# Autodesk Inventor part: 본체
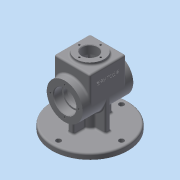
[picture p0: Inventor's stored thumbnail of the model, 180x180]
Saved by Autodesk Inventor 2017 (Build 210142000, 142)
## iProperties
Created: 2020-07
Part Number: 본체
Material: 알루미늄 6061
Document SubType Name: Modeling
Designer: mduedu
Density: 2.71 g/cm^3
Appearance: 기본값
Mass: 1025.32 g
Surface Area: 854.574 cm^2
Volume: 378.346 cm^3
Author: mduedu
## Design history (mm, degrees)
sketch "스케치1"
  geometry: C1 r 32 at (0, 0); 1 further point
  constraints: 1 centre point, 1 coincident
  dimensions: "d0" = 64 diameter of C1
extrude "돌출1" new body sketch "스케치1" stored distance "d1" = 90; taper "d2" = 0 deg
sketch "스케치3"
  geometry: L1 (0, -32)-(50, -32); L2 (50, -32)-(50, 32); L3 (50, 32)-(0, 32); L4 (0, 32)-(0, -32); C1 r 32 at (0, 0) reference; 2 further points
  constraints: 8 end point, 2 parallel, 1 coincident, 1 horizontal, 1 midpoint, 1 perpendicular, 1 tangent
  dimensions: "d5" = 50 distance of L2.end L3.end
extrude "돌출2" join sketch "스케치3" stored distance "d7" = 64; taper "d8" = 0 deg
sketch "스케치4"
  geometry: C1 r 25 at (32, 32); 1 further point
  constraints: 1 centre point, 1 coincident
  dimensions: "d9" = 50 diameter of C1
extrude "돌출3" join sketch "스케치4" distance "d10" = 5; taper "d11" = 0 deg
sketch "스케치5"
  geometry: L1 (0, -25)-(40, -25); L2 (40, -25)-(40, 25); L3 (40, 25)-(0, 25); L4 (0, 25)-(0, -25); L5 (55, -25)-(55, 25) reference; A1 r 25 centre (0, 0) between (0, 25) and (0, -25); A2 r 25 centre (0, 0) between (0, -25) and (0, 25); 2 further points
  constraints: 8 end point, 4 point on circle, 2 centre point, 2 coincident, 2 parallel, 1 horizontal, 1 midpoint, 1 perpendicular, 1 tangent
  dimensions: "d12" = 50 diameter of A1; "d13" = 15 distance between parallel lines of L2 L5
extrude "돌출4" cut sketch "스케치5" stored distance "d14" = 48; taper "d15" = 0 deg
sketch "스케치6"
  geometry: C1 r 20 at (0, 0); 1 further point
  constraints: 1 centre point, 1 coincident
  dimensions: "d16" = 40 diameter of C1
extrude "돌출5" cut sketch "스케치6" distance "d17" = 15; taper "d18" = 0 deg
sketch "스케치7"
  geometry: C1 r 17 at (0, 0); 1 further point
  constraints: 1 centre point, 1 coincident
  dimensions: "d19" = 34 diameter of C1
extrude "돌출6" cut sketch "스케치7" stored distance "d20" = 15; taper "d21" = 0 deg
fillet "모깎기1" dims "d22" = 3
fillet "모깎기2" dims "d23" = 3
fillet "모깎기3" dims "d24" = 3
fillet "모깎기4" dims "d25" = 3
fillet "모깎기5" dims "d26" = 3
sketch "스케치8"
  geometry: C1 r 14 at (0, 0); 1 further point
  constraints: 1 centre point, 1 coincident
  dimensions: "d27" = 28 diameter of C1
extrude "돌출7" cut sketch "스케치8" stored distance "d28" = 15; taper "d29" = 0 deg
node "작업 평면1"
sketch "스케치9"
  geometry: C1 r 67.5 at (0, 0); 1 further point
  constraints: 1 centre point, 1 coincident
  dimensions: "d31" = 135 diameter of C1
extrude "돌출8" join sketch "스케치9" distance "d33" = 10; taper "d34" = 0 deg
sketch "스케치10"
  geometry: C1 r 15 at (0, 0); 1 further point
  constraints: 1 centre point, 1 coincident
  dimensions: "d35" = 30 diameter of C1
extrude "돌출9" join sketch "스케치10" stored distance "d39" = 10; taper "d40" = 0 deg
sketch "스케치11"
  geometry: L1 (-35, -5)-(35, -5); L2 (35, -5)-(35, 5); L3 (35, 5)-(-35, 5); L4 (-35, 5)-(-35, -5); L5 (-35, -5)-(35, 5); L6 (35, -5)-(-35, 5); 1 further point
  constraints: 12 end point, 2 midpoint, 2 parallel, 1 horizontal, 1 perpendicular
  dimensions: "d41" = 70 distance of L3.end L2.end; "d42" = 10 distance of L2.end L1.end
extrude "돌출10" join sketch "스케치11" stored distance "d43" = 10; taper "d44" = 0 deg
sketch "스케치12"
  geometry: L1 (-5, -32)-(5, -32); L2 (5, -32)-(5, 32); L3 (5, 32)-(-5, 32); L4 (-5, 32)-(-5, -32); L5 (-5, -32)-(5, 32); L6 (5, -32)-(-5, 32); 1 further point
  constraints: 12 end point, 2 midpoint, 2 parallel, 1 horizontal, 1 perpendicular
  dimensions: "d45" = 10 distance of L3.end L2.end; "d46" = 64 distance of L2.end L1.end
extrude "돌출11" join sketch "스케치12" stored distance "d47" = 10; taper "d48" = 0 deg; dims "d12" = 50, "d13" = 15, "d27" = 28
fillet "모깎기6" dims "d50" = 3
fillet "모깎기7" dims "d51" = 3
sketch "스케치13" dims "d52" = 112
  geometry: 3 further points
  constraints: 2 horizontal alignment, 1 coincident, 2 other
hole "구멍1" sketch "스케치13" at (-56, 0) diameter "d54" = 9; stored, may be unused: countersink angle "d58" = 90 deg, drill point angle "d60" = 118 deg; dims "d55" = 6, "d56" = 4, "d57" = 2, "d59" = 8
fillet "모깎기8" dims "d64" = 3
sketch "스케치14" dims "d67" = 50
  geometry: 3 further points
  constraints: 2 vertical alignment, 1 coincident, 2 other
hole "구멍2" sketch "스케치14" at (0, 25) diameter "d68" = 3.242; stored, may be unused: countersink angle "d72" = 90 deg, drill point angle "d74" = 118 deg; dims "d69" = 7, "d70" = 4, "d71" = 2, "d73" = 9
sketch "스케치15" dims "d78" = 38
  geometry: 3 further points
  constraints: 2 vertical alignment, 1 coincident, 2 other
hole "구멍3" sketch "스케치15" at (0, 19) diameter "d79" = 3.242; stored, may be unused: countersink angle "d83" = 90 deg, drill point angle "d85" = 118 deg; dims "d80" = 8, "d81" = 4, "d82" = 2, "d84" = 10
fillet "모깎기9" dims "d89" = 0.3
chamfer "모따기1" distance "d90" = 1; stored, may be unused: second distance "d91" = 2, angle "d92" = 45 deg
chamfer "모따기2" distance "d93" = 1; stored, may be unused: second distance "d94" = 2, angle "d95" = 45 deg
sketch "스케치16"
  geometry: L1 (-3, 0)-(-3, -27.404) reference; L2 (54, 8)-(4, 8) reference; 2 further points
  constraints: 1 other
  dimensions: "d96" = 32 distance from line of point (29, -17) L1; "d97" = 25 distance from line of point (29, -17) L2
feature "엠보싱1" sketch "스케치16" dims "d0" = 64, "d98" = 0.5, "d99" = 0
node "솔리드1"
mirror "대칭1"
pattern_circular "원형 패턴1" dims angle "d62" = 360 deg
pattern_circular "원형 패턴2" dims angle "d76" = 360 deg
mirror "대칭2"
pattern_circular "원형 패턴3" dims angle "d87" = 360 deg
other parameters: "d30" = -65
